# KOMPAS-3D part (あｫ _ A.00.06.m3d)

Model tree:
1. Эскиз:1
2. Операция выдавливания:1
     Расстояние 1 = 160
3. Эскиз:2
4. Операция выдавливания:2
     Расстояние 1 = 28
5. M8 - Условное изображение:1
     Длина резьбы = 12; Шаг резьбы = 1.25; Номинальный диаметр резьбы = 8
6. Подгонка:1
7. M12x1.5 - Условное изображение:2
     Длина резьбы = 160; Шаг резьбы = 1.5; Номинальный диаметр резьбы = 12
8. Подгонка:2
9. Эскиз:3
10. Операция выдавливания:3
     Расстояние 1 = 20; Расстояние 2 = 2
11. Эскиз:4
12. Вырезать элемент выдавливания:1
     Расстояние 1 = 10
13. Фаска:1
     Угол = 45; Длина 1 = 1; Длина 2 = 1
14. Эскиз:5
15. Операция выдавливания:4
     Расстояние 1 = 16
16. Эскиз:6
17. Вырезать элемент выдавливания:2  (labels: Сталь 40Х  ГОСТ 4543-71; A.00.06)
     Расстояние 2 = 8.5; Расстояние 1 = 8.5

Referenced files in C:\Program Files (x86)\ASCON\KOMPAS-3D V15\Sys\Thread\: cil1_24705-2004.xml
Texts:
  Сталь 40Х  ГОСТ 4543-71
